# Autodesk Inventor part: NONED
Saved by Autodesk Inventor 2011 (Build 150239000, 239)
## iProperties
Created: 2007-10
Part Number: NONED
Document SubType Name: Modeling
Density: 1 g/cm^3
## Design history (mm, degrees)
feature "Base1"
body "Solid1"
